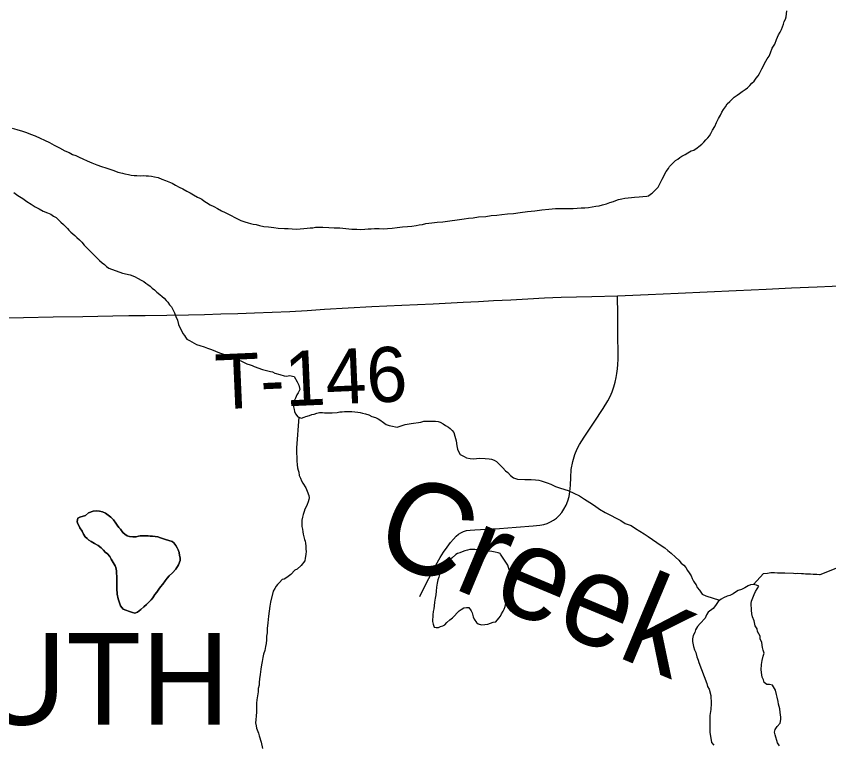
# Model space of a CAD drawing. Extents: x 103424 to 286016, y 38711 to 110967.
# Drawn here: x 121647 to 126106, y 49155 to 53149 of the extents above; entities that cross this region are included whole.
import ezdxf

# ---------------------------------------------------------------- set-up
doc = ezdxf.new("R2010")
doc.units = 0
for name, color, linetype in [('GM_X_Corporation_Text', 7, 'Continuous'), ('GM_X_Minor_Lake', 7, 'Continuous'), ('GM_X_Minor_River', 7, 'Continuous'), ('GM_X_Minor_River_Text', 7, 'Continuous'), ('GM_X_Township_Road', 7, 'Continuous'), ('GM_X_Township_Road_Text', 7, 'Continuous')]:
    doc.layers.add(name, color=color, linetype=linetype)

msp = doc.modelspace()

# ---------------------------------------------------------------- linework, layer by layer
at = {"layer": 'GM_X_Minor_Lake'}
for points in [[(122027.1, 50408.3), (122042.9, 50422.7), (122069, 50431.2), (122089.2, 50433.6), (122103.3, 50431.8), (122119.5, 50428), (122135.8, 50420.2), (122152.1, 50410.4), (122166.5, 50398.5), (122180.8, 50384.6), (122193.2, 50366.6), (122201.5, 50354.6), (122209.8, 50342.6), (122218, 50332.7), (122232.4, 50314.7), (122242.7, 50304.8), (122254.9, 50296.9), (122269.1, 50293.1), (122287.3, 50291.4), (122305.5, 50291.7), (122317.5, 50293.9), (122327.6, 50296.1), (122337.7, 50296.3), (122357.9, 50296.6), (122369.9, 50296.8), (122382.1, 50295), (122394.2, 50295.2), (122408.3, 50293.4), (122424.5, 50291.6), (122438.7, 50285.8), (122465.1, 50276.1), (122501.7, 50264.6), (122511.8, 50258.7), (122522.2, 50242.7), (122530.5, 50230.7), (122534.7, 50218.7), (122541, 50204.7), (122543.3, 50188.5), (122545.5, 50176.4), (122545.8, 50160.3), (122538.1, 50137.9), (122522.4, 50113.4), (122504.6, 50092.9), (122486.7, 50076.5), (122474.8, 50064.2), (122464.9, 50049.9), (122451.1, 50031.5), (122439.2, 50017.1), (122429.4, 50002.8), (122417.6, 49986.5), (122407.7, 49974.2), (122395.9, 49955.8), (122388, 49945.6), (122376.1, 49933.3), (122362.2, 49918.9), (122346.3, 49906.5), (122330.4, 49892.1), (122312.4, 49877.7), (122298.4, 49871.4), (122284.2, 49875.2), (122268, 49881), (122247.7, 49888.8), (122233.5, 49894.6), (122219, 49912.5), (122212.7, 49928.6), (122206.3, 49950.7), (122199.8, 49976.8), (122199.3, 50007.1), (122198.6, 50045.5), (122198.2, 50073.8), (122197.8, 50092), (122197.7, 50104.1), (122193.3, 50122.2), (122189.1, 50132.2), (122168.3, 50168.2), (122160, 50182.2), (122147.6, 50198.2), (122135.4, 50206.1), (122125.1, 50218), (122112.8, 50230), (122096.4, 50243.8), (122076.1, 50253.6), (122057.7, 50265.4), (122045.5, 50273.3), (122035.2, 50281.2), (122025, 50291.1), (122016.7, 50305.1), (122008.3, 50321.2), (121995.9, 50341.2), (121989.6, 50353.2), (121983.4, 50365.2), (121981.2, 50375.3), (121984.9, 50393.5), (121994.9, 50399.7), (122027.1, 50408.3)], [(122439.2, 50017.1), (122451.1, 50031.5), (122464.9, 50049.9), (122474.8, 50064.2), (122486.7, 50076.5), (122504.6, 50092.9), (122522.4, 50113.4), (122538.1, 50137.9), (122545.8, 50160.3), (122545.5, 50176.4), (122543.3, 50188.5), (122541, 50204.7), (122534.7, 50218.7), (122530.5, 50230.7), (122522.2, 50242.7), (122511.8, 50258.7), (122501.7, 50264.6), (122465.1, 50276.1), (122438.7, 50285.8), (122424.5, 50291.6), (122408.3, 50293.4), (122394.2, 50295.2), (122382.1, 50295), (122369.9, 50296.8), (122357.9, 50296.6), (122337.7, 50296.3), (122327.6, 50296.1), (122317.5, 50293.9), (122305.5, 50291.7), (122287.3, 50291.4), (122269.1, 50293.1), (122254.9, 50296.9), (122242.7, 50304.8), (122232.4, 50314.7), (122218, 50332.7), (122209.8, 50342.6), (122201.5, 50354.6), (122193.2, 50366.6), (122180.8, 50384.6), (122166.5, 50398.5), (122152.1, 50410.4), (122135.8, 50420.2), (122119.5, 50428), (122103.3, 50431.8), (122089.2, 50433.6), (122069, 50431.2), (122042.9, 50422.7), (122027.1, 50408.3)], [(122027.1, 50408.3), (121994.9, 50399.7), (121984.9, 50393.5), (121981.2, 50375.3), (121983.4, 50365.2), (121989.6, 50353.2), (121995.9, 50341.2), (122008.3, 50321.2), (122016.7, 50305.1), (122025, 50291.1), (122035.2, 50281.2), (122045.5, 50273.3), (122057.7, 50265.4), (122076.1, 50253.6), (122096.4, 50243.8), (122112.8, 50230), (122125.1, 50218), (122135.4, 50206.1), (122147.6, 50198.2), (122160, 50182.2), (122168.3, 50168.2), (122189.1, 50132.2), (122193.3, 50122.2), (122197.7, 50104.1), (122197.8, 50092), (122198.2, 50073.8), (122198.6, 50045.5), (122199.3, 50007.1), (122199.8, 49976.8), (122206.3, 49950.7), (122212.7, 49928.6), (122219, 49912.5), (122233.5, 49894.6), (122247.7, 49888.8), (122268, 49881), (122284.2, 49875.2), (122298.4, 49871.4), (122312.4, 49877.7), (122330.4, 49892.1), (122346.3, 49906.5), (122362.2, 49918.9), (122376.1, 49933.3), (122388, 49945.6), (122395.9, 49955.8), (122407.7, 49974.2), (122417.6, 49986.5), (122429.4, 50002.8), (122439.2, 50017.1)], [(124304.8, 50195.2), (124302.8, 50199.2), (124290.6, 50203), (124274.4, 50206.8), (124256.1, 50210.6), (124240, 50212.3), (124221.7, 50216.1), (124199.5, 50217.7), (124187.4, 50219.5), (124175.3, 50219.3), (124163.1, 50221.1), (124149, 50220.9), (124136.9, 50220.7), (124122.8, 50218.5), (124108.8, 50214.2), (124094.8, 50207.9), (124080.7, 50203.6), (124068.7, 50199.4), (124058.7, 50193.2), (124036.8, 50174.6), (124026.8, 50166.4), (124011, 50148), (124001.1, 50137.7), (123993.2, 50125.4), (123985.4, 50113.2), (123977.5, 50103), (123971.6, 50090.7), (123965.9, 50070.4), (123960.1, 50054.2), (123956.4, 50035.9), (123952.7, 50013.7), (123951.1, 49993.4), (123949.4, 49973.2), (123945.7, 49955), (123942, 49932.7), (123940.3, 49912.5), (123938.6, 49896.3), (123934.8, 49880.1), (123933.1, 49861.8), (123931.7, 49825.5), (123933.9, 49811.4), (123940.3, 49795.3), (123950.4, 49793.5), (123964.5, 49793.7), (123974.5, 49797.9)], [(124304.8, 50195.2), (124302.8, 50199.2), (124290.6, 50203), (124274.4, 50206.8), (124256.1, 50210.6), (124240, 50212.3), (124221.7, 50216.1), (124199.5, 50217.7), (124187.4, 50219.5), (124175.3, 50219.3), (124163.1, 50221.1), (124149, 50220.9), (124136.9, 50220.7), (124122.8, 50218.5), (124108.8, 50214.2), (124094.8, 50207.9), (124080.7, 50203.6), (124068.7, 50199.4), (124058.7, 50193.2), (124036.8, 50174.6), (124026.8, 50166.4), (124011, 50148), (124001.1, 50137.7), (123993.2, 50125.4), (123985.4, 50113.2), (123977.5, 50103), (123971.6, 50090.7), (123965.9, 50070.4), (123960.1, 50054.2), (123956.4, 50035.9), (123952.7, 50013.7), (123951.1, 49993.4), (123949.4, 49973.2), (123945.7, 49955), (123942, 49932.7), (123940.3, 49912.5), (123938.6, 49896.3), (123934.8, 49880.1), (123933.1, 49861.8), (123931.7, 49825.5), (123933.9, 49811.4), (123940.3, 49795.3), (123950.4, 49793.5), (123964.5, 49793.7), (123974.5, 49797.9), (123988.6, 49802.2), (123998.6, 49808.4), (124010.5, 49820.7), (124026.4, 49835.1), (124040.3, 49845.4), (124052.2, 49857.7), (124066.1, 49874.1), (124078, 49884.4), (124088, 49892.7), (124104, 49901), (124118, 49903.3), (124130.2, 49903.5), (124142.6, 49885.5), (124148.8, 49873.5), (124155.2, 49851.4), (124159.5, 49839.3), (124171.9, 49821.3), (124182.1, 49813.4), (124200.4, 49807.6), (124218.5, 49810), (124234.6, 49812.2), (124248.7, 49816.5), (124264.7, 49822.8), (124278.8, 49825.1), (124294.6, 49843.5), (124304.5, 49855.8), (124310.4, 49868), (124318.2, 49882.3), (124324, 49894.5), (124329.8, 49908.7), (124333.6, 49925), (124339.3, 49943.3), (124343, 49963.5), (124346.7, 49985.8), (124350.4, 50006.1), (124352.1, 50026.3), (124355.8, 50042.5), (124355.7, 50052.6), (124357.5, 50066.8), (124357.1, 50084.9), (124354.9, 50099), (124352.7, 50111.1), (124348.4, 50123.2), (124344.2, 50135.2), (124304.8, 50195.2)], [(123974.5, 49797.9), (123988.6, 49802.2), (123998.6, 49808.4), (124010.5, 49820.7), (124026.4, 49835.1), (124040.3, 49845.4), (124052.2, 49857.7), (124066.1, 49874.1), (124078, 49884.4), (124088, 49892.7), (124104, 49901), (124118, 49903.3), (124130.2, 49903.5), (124142.6, 49885.5), (124148.8, 49873.5), (124155.2, 49851.4), (124159.5, 49839.3), (124171.9, 49821.3), (124182.1, 49813.4), (124200.4, 49807.6), (124218.5, 49810), (124234.6, 49812.2), (124248.7, 49816.5), (124264.7, 49822.8), (124278.8, 49825.1), (124294.6, 49843.5), (124304.5, 49855.8), (124310.4, 49868), (124318.2, 49882.3), (124324, 49894.5), (124329.8, 49908.7), (124333.6, 49925), (124339.3, 49943.3), (124343, 49963.5), (124346.7, 49985.8), (124350.4, 50006.1), (124352.1, 50026.3), (124355.8, 50042.5), (124355.7, 50052.6), (124357.5, 50066.8), (124357.1, 50084.9), (124354.9, 50099), (124352.7, 50111.1), (124348.4, 50123.2), (124344.2, 50135.2), (124304.8, 50195.2)], [(125722.7, 50020), (125709.3, 50025.5), (125691.1, 50029.3), (125677, 50027), (125662.9, 50022.8), (125645, 50010.5), (125626.9, 50002.2), (125608.8, 49995.9), (125594.8, 49987.6), (125580.9, 49977.4), (125562.8, 49969), (125548.8, 49964.8), (125528.7, 49956.5), (125514.7, 49948.2), (125498.7, 49935.9), (125484.9, 49913.5), (125471.1, 49897.2), (125443.1, 49876.7), (125435.2, 49862.5), (125427.5, 49844.2), (125399.6, 49815.6), (125385.7, 49799.3), (125373.9, 49781), (125370.1, 49764.8), (125362.3, 49748.6), (125358.5, 49730.4), (125358.7, 49716.3), (125363.2, 49688.1), (125369.5, 49670.1), (125375.8, 49656), (125382.2, 49631.9), (125388.5, 49613.9), (125393.2, 49601.7)], [(125835.6, 49144.2), (125825.2, 49160.2), (125812.5, 49204.4), (125808.2, 49218.4), (125812, 49232.6), (125821.9, 49248.9), (125839.8, 49267.2), (125843.5, 49287.4), (125843.3, 49301.6), (125838.9, 49325.7), (125836.6, 49345.8), (125830.1, 49371.9), (125827.9, 49386), (125823.5, 49410.2), (125819.2, 49426.2), (125812.8, 49448.3), (125796.3, 49476.3), (125780.1, 49480.1), (125765.9, 49479.9), (125751.6, 49491.8), (125747.4, 49505.9), (125741.1, 49519.9), (125738.9, 49534), (125734.5, 49560.1), (125736, 49590.4), (125739.7, 49612.6), (125745.4, 49634.9), (125751.2, 49653.1), (125744.9, 49669.1), (125742.7, 49683.2), (125738.2, 49711.4), (125729.9, 49731.4), (125729.6, 49745.5), (125715.1, 49771.5), (125712.9, 49785.6), (125702.6, 49801.6), (125696.1, 49829.7), (125687.7, 49851.8), (125683.4, 49867.9), (125681.1, 49888), (125680.5, 49924.3), (125682.4, 49938.4), (125695.9, 49974.9), (125703.8, 49991.1), (125722.7, 50020)], [(125393.2, 49601.7), (125436.9, 49485.5), (125441.2, 49469.4), (125449.4, 49455.4), (125458.1, 49419.3), (125460.7, 49375), (125459.2, 49342.7), (125453.6, 49310.3), (125452.6, 49245.8), (125453, 49217.6)], [(125453, 49217.6), (125461.9, 49161.3), (125474.3, 49147.3)]]:
    msp.add_lwpolyline(points, dxfattribs=at)
at = {"layer": 'GM_X_Minor_River'}
for points in [[(125184.5, 52239.8), (125192.3, 52254), (125213.8, 52296.8), (125225.6, 52313.2), (125231.5, 52323.4), (125245.4, 52337.7), (125265.3, 52356.3), (125277.2, 52364.5), (125289.2, 52372.8), (125299.2, 52381.1), (125317.2, 52389.4), (125333.2, 52399.8), (125351.1, 52410.2), (125365.2, 52414.5), (125383.1, 52426.9), (125393.1, 52433.1), (125409, 52447.5), (125421, 52457.8), (125430.8, 52470.1), (125442.8, 52482.4), (125450.6, 52492.6), (125458.5, 52504.9), (125468.3, 52523.2), (125480.1, 52543.6), (125489.8, 52566), (125501.5, 52588.4), (125511.3, 52606.7), (125519.1, 52623), (125528.9, 52637.3), (125538.8, 52651.6), (125548.6, 52668), (125562.5, 52680.3), (125574.4, 52692.6), (125586.3, 52704.9), (125602.3, 52715.3), (125616.2, 52725.6), (125630.2, 52736), (125646.2, 52746.3), (125660.1, 52756.6), (125672, 52769), (125683.9, 52781.3), (125695.8, 52793.6), (125707.6, 52810), (125717.5, 52822.2), (125725.4, 52834.5), (125733.2, 52848.8), (125739.1, 52861), (125760.6, 52901.7), (125768.4, 52916), (125778.3, 52930.3), (125786, 52948.6), (125795.7, 52973), (125809.5, 52995.4), (125819.1, 53021.9), (125830.8, 53046.3), (125838.6, 53062.6), (125846.4, 53076.9), (125852.2, 53091.1), (125858.1, 53105.3), (125861.9, 53119.5), (125867.7, 53133.8), (125871.5, 53146), (125875, 53178.3)], [(121624, 52534.9), (121650.3, 52527.3), (121680.8, 52517.7), (121703.1, 52510), (121725.4, 52502.3), (121749.8, 52492.6), (121829.1, 52455.5), (121855.6, 52441.8), (121884.1, 52426.1), (121912.6, 52410.4), (121937, 52400.7), (121955.3, 52390.9), (121973.6, 52385.1), (121991.9, 52375.3), (122012.2, 52365.6), (122036.6, 52355.9), (122061, 52344.1), (122089.5, 52332.5), (122113.8, 52324.8), (122138.2, 52317.1), (122160.5, 52309.4), (122182.8, 52301.7), (122205.1, 52294), (122229.5, 52288.3), (122243.6, 52284.5), (122261.9, 52280.8), (122278.1, 52277), (122294.3, 52275.2), (122308.4, 52275.5), (122326.6, 52273.8), (122344.7, 52274.1), (122358.9, 52272.3), (122373, 52272.5), (122389.2, 52270.7), (122405.4, 52267), (122425.6, 52263.3), (122445.9, 52255.5), (122466.2, 52247.8), (122484.5, 52240), (122502.8, 52232.2), (122521.1, 52222.4), (122541.5, 52210.6), (122561.9, 52200.8), (122582.2, 52189.1), (122600.6, 52179.3), (122618.9, 52169.5), (122641.3, 52155.7), (122653.5, 52149.8), (122665.7, 52144), (122676, 52136.1), (122690.3, 52126.2), (122710.6, 52114.4), (122731, 52104.6), (122751.4, 52092.8), (122773.8, 52081.1)], [(122773.8, 52081.1), (122794.1, 52071.3), (122879.6, 52028.3), (122901.9, 52020.6), (122920.2, 52014.8), (122932.3, 52011), (122946.5, 52007.2), (122962.7, 52005.4), (122980.9, 51999.6), (123005.2, 51994), (123031.5, 51992.4), (123059.8, 51988.8), (123084.1, 51985.2), (123118.4, 51983.7), (123138.6, 51984), (123160.8, 51982.4), (123183.1, 51980.7), (123205.2, 51981.1), (123225.4, 51983.4), (123243.5, 51985.8), (123259.6, 51988.1), (123273.7, 51988.3), (123289.8, 51990.6), (123310, 51990.9), (123330.2, 51991.2), (123362.5, 51989.7), (123390.8, 51988.2), (123423.1, 51986.7), (123455.4, 51983.2), (123487.8, 51979.7), (123516, 51980.1), (123538.2, 51978.5), (123560.4, 51980.9), (123578.6, 51981.2), (123594.7, 51981.4), (123612.8, 51983.7), (123639, 51984.2), (123661.3, 51982.5), (123683.5, 51982.9), (123709.6, 51985.3), (123737.8, 51989.8), (123766, 51992.3), (123794.3, 51994.8), (123818.4, 51997.2), (123840.6, 51999.6), (123858.7, 52003.9), (123876.8, 52006.2), (123894.9, 52010.6), (123927.1, 52015.1), (123957.3, 52017.7), (123987.5, 52020.2), (124013.7, 52024.6), (124080.1, 52033.8), (124104.3, 52036.2), (124128.4, 52040.7), (124154.6, 52043.1), (124182.8, 52047.6), (124223.1, 52050.3), (124253.3, 52054.8), (124283.5, 52057.3), (124311.8, 52059.8), (124341.9, 52064.4), (124376.2, 52066.9), (124412.5, 52071.6), (124452.7, 52076.3), (124493, 52081), (124531.3, 52085.7), (124569.5, 52090.3), (124605.8, 52092.9), (124650.2, 52093.7), (124678.4, 52094.1), (124702.6, 52094.5), (124724.8, 52094.9), (124747, 52097.3), (124767.2, 52097.6), (124787.3, 52100), (124807.5, 52102.3), (124827.6, 52106.7), (124845.7, 52109), (124863.8, 52113.3), (124885.9, 52119.7), (124903.9, 52126.1), (124924, 52132.5), (124938, 52136.8), (124952.1, 52143), (124970.1, 52147.4), (124986.2, 52149.7), (125004.4, 52152), (125022.5, 52154.3), (125040.6, 52156.6), (125064.8, 52157), (125085, 52159.4), (125107.1, 52161.7), (125117.2, 52163.9), (125127.1, 52172.2), (125137.1, 52178.4), (125149, 52190.7), (125160.9, 52201), (125168.8, 52211.2), (125176.7, 52225.5), (125184.5, 52239.8)], [(121634, 52181.6), (121656.4, 52165.8), (121683, 52148.1), (121705.4, 52132.3), (121727.9, 52116.5), (121750.3, 52102.7), (121772.7, 52090.9), (121795.1, 52079.2), (121817.5, 52069.5), (121835.7, 52061.7), (121852.1, 52051.8), (121866.3, 52044), (121878.6, 52032.1), (121891, 52018.1), (121905.3, 52006.3), (121917.6, 51994.3), (121927.9, 51984.4), (121936.1, 51974.4), (121946.4, 51964.5), (121956.6, 51954.6), (121968.9, 51944.7), (121979.1, 51934.7), (121993.5, 51920.8), (122005.8, 51908.9), (122020.2, 51893), (122040.7, 51871.1), (122057.2, 51853.2), (122075.7, 51835.3), (122090, 51821.4), (122104.4, 51807.5), (122118.7, 51795.6), (122131, 51785.7), (122141.2, 51775.8), (122155.5, 51765.9), (122230.6, 51738.9), (122271.2, 51729.4), (122295.5, 51719.7), (122315.9, 51710), (122332.2, 51700.1), (122346.4, 51692.3), (122358.7, 51684.4), (122368.9, 51676.5), (122381.2, 51666.6)], [(122381.2, 51666.6), (122393.5, 51656.7), (122405.7, 51646.8), (122418, 51634.9), (122434.4, 51621), (122446.7, 51611.1), (122459, 51601.2), (122469.3, 51589.2), (122479.5, 51579.3), (122487.8, 51565.3), (122498.1, 51553.4), (122506.4, 51539.4), (122514.8, 51521.3), (122523.2, 51501.2), (122531.6, 51481.2), (122538.1, 51457.1), (122546.5, 51437), (122554.8, 51421), (122561.1, 51406.9), (122569.3, 51397), (122575.6, 51387), (122583.8, 51377), (122598.1, 51369.2), (122610.3, 51361.3), (122622.6, 51353.4), (122636.8, 51347.6), (122655, 51341.8), (122677.4, 51334.1), (122695.6, 51326.3), (122718, 51318.6), (122740.3, 51310.9), (122762.7, 51301.1), (122785, 51293.4), (122809.4, 51283.7), (122833.8, 51274), (122856.1, 51264.3), (122878.4, 51256.6), (122896.7, 51248.8), (122913, 51241), (122931.3, 51235.2), (122941.4, 51231.3), (122951.6, 51225.5), (122998.3, 51210.1), (123020.6, 51204.4), (123042.9, 51198.7), (123053, 51196.8), (123065.2, 51188.9), (123093.6, 51181.3), (123117.9, 51175.7), (123132.1, 51173.9), (123146.2, 51176.1), (123172.5, 51170.5), (123189.1, 51142.5), (123197.5, 51124.4), (123203.9, 51100.3), (123194.2, 51082), (123186.3, 51069.7), (123178.5, 51051.4), (123172.7, 51037.2), (123169, 51018.9), (123169.2, 51004.8), (123171.5, 50990.7), (123173.7, 50978.6), (123180, 50966.6), (123192.3, 50950.6), (123212.6, 50942.9), (123226.7, 50947.2), (123236.7, 50951.4), (123256.8, 50957.8), (123268.8, 50962), (123280.9, 50964.2), (123296.9, 50970.5), (123311, 50972.8), (123327.2, 50973), (123339.3, 50971.2), (123351.4, 50971.4), (123369.6, 50971.7), (123379.6, 50971.9), (123407.8, 50974.4), (123421.9, 50976.6), (123436.1, 50976.8), (123448.1, 50979.1), (123460.2, 50979.3), (123472.3, 50979.5), (123488.5, 50979.7), (123504.6, 50978), (123520.8, 50976.2), (123535, 50974.4), (123547.1, 50970.6), (123563.4, 50966.8), (123581.6, 50961.1), (123597.9, 50951.2), (123618.2, 50945.5), (123632.4, 50939.7), (123642.6, 50933.8), (123663.1, 50918), (123677.3, 50908.1), (123693.6, 50902.3), (123711.8, 50898.5), (123728, 50894.8), (123738.1, 50892.9)], [(123197.4, 50948.7), (123185.1, 50778.8), (123185.6, 50750.5), (123186, 50728.3), (123186.3, 50708.1), (123188.7, 50686), (123191, 50669.8), (123193.2, 50657.7), (123197.5, 50645.7), (123199.8, 50627.5), (123206.1, 50613.5), (123212.4, 50597.5), (123218.7, 50585.4), (123235.2, 50559.5), (123243.6, 50541.4), (123252.1, 50517.3), (123254.3, 50505.2), (123252.5, 50495.1), (123248.6, 50482.9), (123242.8, 50468.7), (123237, 50456.5), (123231.2, 50442.2), (123227.3, 50430), (123221.6, 50413.8), (123217.8, 50399.6), (123214, 50383.3), (123214.3, 50363.2), (123214.6, 50347), (123216.9, 50332.9), (123219.1, 50318.8), (123221.4, 50304.7), (123225.7, 50290.6), (123227.9, 50276.5), (123232.1, 50266.5), (123234.3, 50256.4), (123236.6, 50240.3), (123236.9, 50224.1), (123237.1, 50210), (123235.3, 50195.8), (123233.5, 50183.7), (123231.7, 50173.6), (123229.9, 50159.4), (123210.1, 50132.8), (123188.3, 50114.3), (123176.3, 50108), (123154.5, 50083.4), (123132.6, 50066.9), (123116.6, 50058.5), (123106.5, 50056.4), (123090.6, 50039.9), (123080.7, 50029.7), (123072.8, 50019.5), (123065, 50007.2), (123057.1, 49992.9), (123042, 49932.1), (123038.4, 49909.8), (123034.8, 49883.5), (123031.2, 49855.1), (123027.8, 49818.7), (123024.3, 49788.4), (123024.7, 49764.1), (123020.9, 49745.9), (123019.3, 49725.7), (123017.6, 49705.4), (123013.8, 49689.2), (123010.2, 49666.9), (123004.4, 49646.6), (123000.7, 49628.4), (122997.1, 49606.1), (122993.3, 49587.9), (122989.7, 49563.6), (122986.2, 49535.2), (122982.5, 49510.9), (122980.8, 49490.7), (122979.1, 49476.5), (122975.3, 49458.3), (122973.6, 49440.1), (122970, 49417.8), (122966.3, 49395.5), (122964.6, 49377.3), (122965, 49353.1), (122965.4, 49328.8), (122963.7, 49308.6), (122962.1, 49286.4), (122960.4, 49270.2), (122962.6, 49254.1), (122964.9, 49240), (122975.4, 49213.9), (122979.7, 49197.8), (122990.4, 49163.6), (122999.1, 49129.4)], [(123738.1, 50892.9), (123780.3, 50907.8), (123814.5, 50912.3), (123866.8, 50921.3), (123882.9, 50925.6), (123909.1, 50926), (123947.4, 50926.6), (123961.6, 50924.9), (123973.8, 50921), (123990.1, 50911.2), (124002.4, 50901.3), (124018.6, 50893.5), (124028.8, 50885.6), (124039.1, 50875.6), (124047.4, 50863.6), (124053.8, 50843.6), (124060.3, 50817.4), (124064.7, 50791.2), (124069.1, 50773.1), (124075.4, 50755), (124083.7, 50743), (124104.1, 50731.3), (124118.3, 50725.4), (124138.6, 50721.7), (124156.7, 50720), (124189, 50722.5), (124219.3, 50721), (124241.5, 50719.4), (124255.7, 50717.6), (124269.9, 50711.8), (124282.1, 50703.9), (124300.6, 50686), (124317, 50670.1), (124331.4, 50654.2), (124343.7, 50644.3), (124360.1, 50628.4), (124376.5, 50614.5), (124396.8, 50606.8), (124437.2, 50605.4), (124455.3, 50605.7), (124473.5, 50606), (124495.7, 50604.3), (124513.9, 50602.6), (124528.1, 50598.8), (124544.3, 50593), (124560.6, 50587.2), (124580.9, 50579.5), (124605.3, 50567.8), (124633.7, 50558.1), (124676.3, 50544.7), (124706.8, 50531.1), (124737.3, 50515.4), (124765.9, 50497.7), (124794.4, 50480), (124821, 50462.2), (124847.5, 50442.5), (124878.1, 50424.8), (124908.6, 50409.1), (124939.1, 50393.5), (124965.6, 50379.7), (124988.1, 50364), (125020.6, 50352.4), (125045, 50336.6), (125069.5, 50322.9), (125091.9, 50307.1), (125114.4, 50293.3), (125138.9, 50275.5), (125161.4, 50259.7), (125185.8, 50244), (125206.3, 50230.2), (125222.6, 50216.3), (125241.1, 50200.4), (125265.6, 50178.6), (125282.1, 50162.7), (125296.4, 50146.8), (125310.8, 50134.9), (125321.1, 50123), (125331.4, 50107), (125339.7, 50093), (125350.1, 50077), (125356.4, 50062.9), (125362.7, 50046.9), (125370.9, 50036.9), (125377.2, 50026.9), (125383.5, 50012.9), (125395.8, 49999), (125410.3, 49977), (125430.6, 49967.2), (125507, 49942.3)], [(126058.3, 50084.6), (126310.8, 50185.6)], [(125692.8, 50028.9), (125747.4, 50089.6), (125769.6, 50091.9), (125787.7, 50094.2), (125807.9, 50094.6), (125824, 50092.8), (125842.2, 50093.1), (125864.4, 50093.5), (125912.8, 50092.3), (125925, 50090.4), (125935.1, 50090.6), (125955.3, 50088.9), (125967.4, 50089.1), (125977.5, 50087.3), (125987.6, 50087.4), (126005.7, 50087.7), (126019.9, 50085.9), (126030, 50086.1), (126040.1, 50086.3), (126054.2, 50084.5), (126058.3, 50084.6)]]:
    msp.add_lwpolyline(points, dxfattribs=at)
at = {"layer": 'GM_X_Township_Road'}
for points in [[(121552.6, 51492.9), (121687, 51495.6), (121849.2, 51498.6), (122011.4, 51501.5), (122176.4, 51504.1), (122265.1, 51505.5), (122353.8, 51506.9), (122472.6, 51508.2), (122591.4, 51509.5), (122680.5, 51512.1), (122769.6, 51514.7), (122862.2, 51517.3), (122954.7, 51520), (123051.2, 51524.3), (123147.8, 51528.7), (123243, 51534.4), (123338.2, 51540.1), (123468.3, 51547.5), (123598.5, 51554.9), (123763.4, 51562.2), (123849.1, 51566), (123934.8, 51569.8), (124099.6, 51578.7), (124183.2, 51583.1), (124266.8, 51587.6), (124360.5, 51592.7), (124454.2, 51597.7), (124545.6, 51602.6), (124637, 51607.3), (124720.9, 51609.1), (124804.8, 51610.8), (124946.2, 51614.4), (125030.5, 51617.9), (125114.8, 51621.3), (125279.7, 51629), (125438.4, 51636.4), (125597.1, 51643.7), (125762, 51651.2), (125902.1, 51657.6), (126042.1, 51664), (126206.9, 51670.4)], [(123861.3, 49963.6), (123893.6, 50027.5), (123949.3, 50135.2), (123973.4, 50178.3), (123992.2, 50206.4), (124010.8, 50233.4), (124029.7, 50259.1), (124046.4, 50279), (124061.1, 50294.2), (124073, 50304.7), (124087.2, 50313.2), (124101.5, 50320.4), (124118.6, 50325.1), (124137.6, 50328), (124164.2, 50329.9), (124225.9, 50333.2), (124299.5, 50337.1), (124391.2, 50344.1), (124482.9, 50351.2), (124520.4, 50355.5), (124541.8, 50358.8), (124560.8, 50364.1), (124579.3, 50372.6), (124594.5, 50381.6), (124611.1, 50394), (124626.3, 50408.2), (124641, 50425.3), (124652.4, 50442.4), (124664.1, 50464.3), (124673.7, 50487.7), (124680.5, 50512), (124684.5, 50538.6), (124687.8, 50574.7), (124689.7, 50617.4), (124693, 50660.7), (124700.7, 50703.9), (124711.6, 50742.9), (124724.9, 50773.3), (124738.2, 50797.5), (124764.3, 50837.4), (124818.9, 50920.5), (124868.3, 50995.5), (124893.5, 51037.3), (124905.8, 51061.6), (124916.3, 51086.7), (124925.8, 51113.8), (124933.4, 51140.9), (124938.6, 51165.2), (124942.6, 51187), (124946.2, 51213.6), (124948.6, 51237.8), (124949.6, 51265.8), (124950.1, 51292.9), (124948.9, 51401.2), (124947.6, 51509.5), (124946.2, 51614.4)]]:
    msp.add_lwpolyline(points, dxfattribs=at)

# ---------------------------------------------------------------- texts
at = {"layer": 'GM_X_Corporation_Text'}
msp.add_text('SOUTH', height=503.12, rotation=0, dxfattribs=at).set_placement((120463.9, 49259.3))
at = {"layer": 'GM_X_Minor_River_Text'}
msp.add_text('Creek', height=503.43, rotation=337.3282, dxfattribs=at).set_placement((123586.9, 50198.9))
at = {"layer": 'GM_X_Township_Road_Text'}
msp.add_text('T-146', height=301.87, rotation=2.5143, dxfattribs=at).set_placement((122744.7, 50990.3))

doc.saveas('drawing.dxf')
